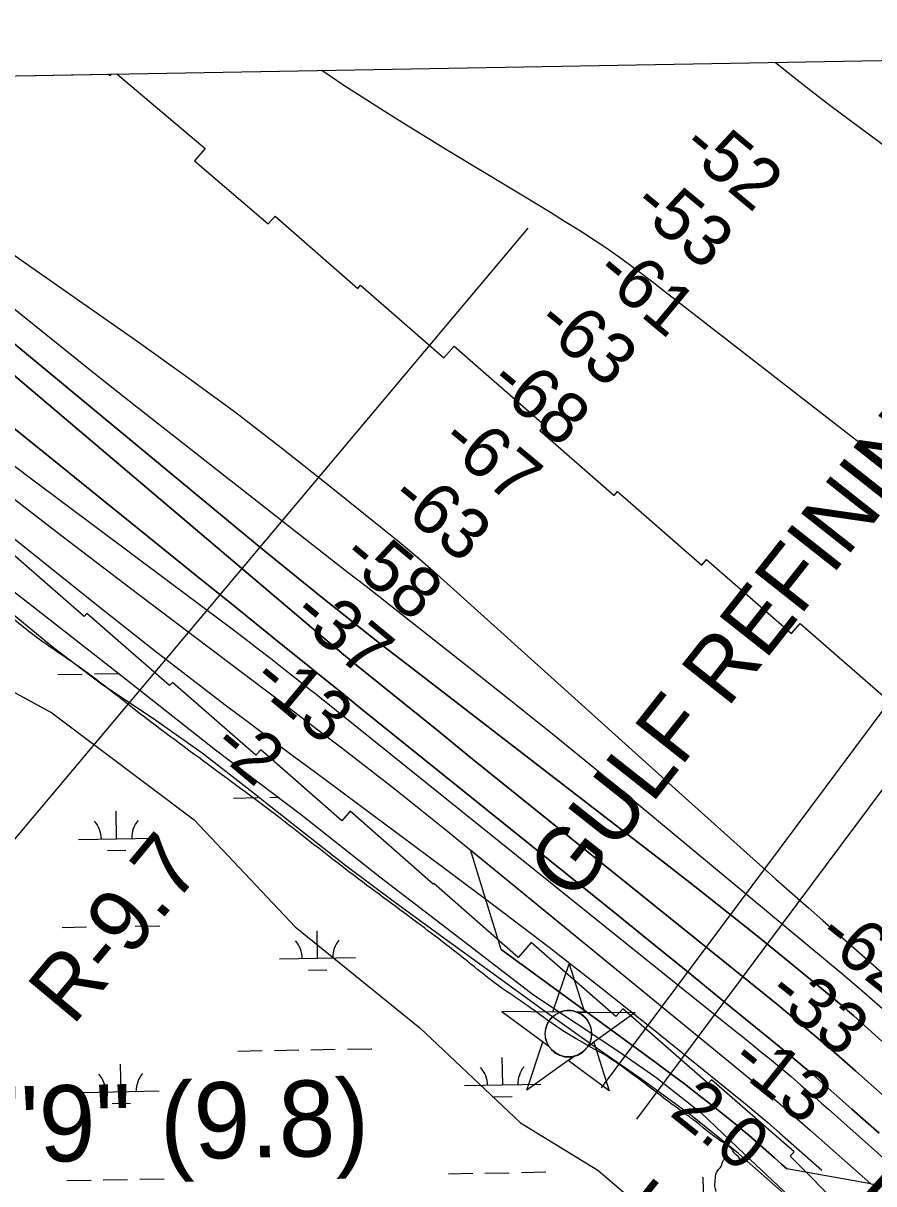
# Model space of a CAD drawing. Extents: x 3903937 to 3942190, y 260677 to 286651.
# Drawn here: x 3915846 to 3916965, y 282879 to 284405 of the extents above; entities that cross this region are included whole.
import ezdxf

# ---------------------------------------------------------------- set-up
doc = ezdxf.new("R2010")
doc.units = 0
for name, color, linetype in [('V-CHAN-NAID', 7, 'Continuous'), ('V-GRID-FRAM', 7, 'Continuous'), ('V-RIVR-EDGE', 7, 'Continuous'), ('V-RIVR-RANG', 7, 'Continuous'), ('V-RIVR-RANG-IDEN', 7, 'Continuous'), ('V-RRAP-FSHR', 7, 'Continuous'), ('V-RRAP-RVMT', 7, 'Continuous'), ('V-SITE-VEGE', 7, 'Continuous'), ('V-TOPO-DPTH', 7, 'Continuous'), ('V-TOPO-MAJR', 7, 'Continuous'), ('V-TOPO-MINR', 7, 'Continuous'), ('V-TOPO-WATR', 7, 'Continuous'), ('V-TOPO-WATR-IDEN', 7, 'Continuous'), ('V-UTIL-IDEN', 7, 'Continuous'), ('V-UTIL-LINE', 7, 'Continuous'), ('V-WETL-SWMP', 7, 'Continuous')]:
    doc.layers.add(name, color=color, linetype=linetype)

msp = doc.modelspace()

# ---------------------------------------------------------------- linework, layer by layer
at = {"layer": 'V-CHAN-NAID'}
for points in [[(3916552.3, 283104.9), (3916542.7, 283105), (3916563.9, 283168.4), (3916584.1, 283104.7), (3916574.5, 283104.7), (3916572.9, 283105.3), (3916570.8, 283105.9), (3916568.8, 283106.4), (3916566.7, 283106.7), (3916565.6, 283106.8), (3916564, 283106.9), (3916562.3, 283106.9), (3916561, 283106.8), (3916559, 283106.6), (3916557.7, 283106.4), (3916555.9, 283106), (3916554.4, 283105.6), (3916553.3, 283105.3)], [(3916552.3, 283104.9), (3916475.8, 283105.4), (3916537.4, 283060), (3916536.3, 283061.9), (3916535.5, 283063.6), (3916534.6, 283065.5), (3916533.9, 283067.6), (3916533.6, 283068.9), (3916533.2, 283070.5), (3916533, 283072), (3916532.8, 283073.6), (3916532.7, 283075.3), (3916532.7, 283076.9), (3916532.8, 283079), (3916533, 283080.6), (3916533.4, 283082.8), (3916533.8, 283084.7), (3916534.4, 283086.6), (3916535.1, 283088.3), (3916535.8, 283089.9), (3916536.6, 283091.4), (3916537.7, 283093.1), (3916538.7, 283094.6), (3916539.7, 283095.9), (3916540.7, 283097), (3916542, 283098.4), (3916543.1, 283099.3), (3916544.8, 283100.7), (3916546, 283101.6), (3916547.7, 283102.7), (3916549.4, 283103.6), (3916550.9, 283104.3)], [(3916574.5, 283104.7), (3916651, 283104.2), (3916588.8, 283059.7), (3916589.7, 283061.2), (3916590.7, 283063), (3916591.4, 283064.6), (3916592.1, 283066.5), (3916592.7, 283068.3), (3916593.1, 283070), (3916593.4, 283072), (3916593.6, 283073.6), (3916593.7, 283075.8), (3916593.7, 283077.8), (3916593.5, 283080), (3916593.3, 283081.8), (3916592.8, 283084), (3916592.1, 283086.2), (3916591.4, 283088.2), (3916590.7, 283089.6), (3916589.7, 283091.5), (3916588.7, 283093.2), (3916587.4, 283094.9), (3916586.2, 283096.5), (3916584.9, 283097.8), (3916583.3, 283099.4), (3916581.5, 283100.8), (3916579.9, 283102), (3916578, 283103.1), (3916576.5, 283103.9)], [(3916570.8, 283046.8), (3916508.5, 283002.2), (3916529.7, 283065.7), (3916537.4, 283060), (3916538, 283059.1), (3916539.4, 283057.2), (3916540.6, 283055.8), (3916542.1, 283054.3), (3916543.5, 283053), (3916544.9, 283051.9), (3916546.3, 283050.9), (3916548, 283049.9), (3916549.7, 283049), (3916551.5, 283048.1), (3916553, 283047.6), (3916554.6, 283047.1), (3916556.8, 283046.5), (3916558.4, 283046.2), (3916560.4, 283045.9), (3916561.9, 283045.8), (3916563.8, 283045.8), (3916565.5, 283045.9), (3916567.2, 283046.1), (3916569.1, 283046.4)], [(3916588.8, 283059.7), (3916596.6, 283065.2), (3916616.8, 283001.5), (3916563, 283041.2), (3916570.8, 283046.8), (3916572.4, 283047.2), (3916574, 283047.8), (3916576.2, 283048.7), (3916577.9, 283049.6), (3916579.8, 283050.7), (3916581.5, 283051.9), (3916583.1, 283053.2), (3916584.4, 283054.3), (3916585.8, 283055.8), (3916587, 283057.2), (3916588.1, 283058.6)]]:
    msp.add_lwpolyline(points, close=True, dxfattribs=at)
msp.add_circle((3916563.2, 283076.4), 30.5, dxfattribs=at)
at = {"layer": 'V-GRID-FRAM'}
msp.add_lwpolyline([(3907892.2, 284196.1), (3939773.2, 284757.2), (3940101.1, 266577.6), (3908204.3, 266016.2), (3907892.2, 284196.1)], dxfattribs=at)
at = {"layer": 'V-RIVR-EDGE'}
msp.add_spline([(3917425.1, 282263.8), (3917389, 282294.2), (3917376.9, 282301.5), (3917364.7, 282305.9), (3917358.9, 282312.7), (3917351.7, 282313.2), (3917339.5, 282313.8), (3917337.6, 282316.7), (3917335.7, 282327.9), (3917333.2, 282330.8), (3917324.5, 282334.2), (3917318.2, 282334.7), (3917313.8, 282338.1), (3917308, 282350.3), (3917295.5, 282366.8), (3917283.8, 282379), (3917272.2, 282386.3), (3917256.7, 282392.6), (3917245, 282398), (3917231.4, 282406.8), (3917219.3, 282412.6), (3917183.4, 282425.8), (3917138.3, 282440), (3917074.7, 282459.6), (3917032, 282479.1), (3916988.4, 282500.1), (3916967.5, 282515.7), (3916953.5, 282531.3), (3916939.4, 282546.9), (3916923.4, 282556.6), (3916909.4, 282558.6), (3916896.3, 282564), (3916886.6, 282574.7), (3916876.4, 282580.1), (3916858.4, 282585), (3916838.5, 282588.4), (3916812.3, 282597.2), (3916792, 282609.9), (3916782.3, 282615.7), (3916776, 282619.6), (3916763.8, 282627.4), (3916749.3, 282634.3), (3916741, 282637.7), (3916730.4, 282642.1), (3916723.6, 282648.4), (3916721.7, 282654.3), (3916721.7, 282661.1), (3916724.1, 282668.3), (3916732.9, 282687.7), (3916733.4, 282696), (3916730.5, 282710.6), (3916725.2, 282723.7), (3916724.8, 282730.5), (3916727.2, 282735.3), (3916735.5, 282744.1), (3916736.9, 282748.4), (3916736.5, 282752.3), (3916730.2, 282755.7), (3916729.2, 282758.2), (3916731.6, 282760.1), (3916731.6, 282763.5), (3916727.8, 282770.8), (3916727.3, 282772.7), (3916727.8, 282778.1), (3916727.8, 282783.9), (3916726.9, 282799), (3916725.5, 282818.4), (3916729.9, 282838.8), (3916731.4, 282846.1), (3916733.8, 282854.8), (3916737.7, 282862.1), (3916742.1, 282864.5), (3916751.8, 282863.5), (3916755.7, 282865.4), (3916757.2, 282868.8), (3916756.2, 282873.2), (3916756.2, 282883.9), (3916757.7, 282894.1), (3916764, 282902.3), (3916767, 282910.1), (3916770.4, 282913), (3916781, 282908.1), (3916789.3, 282907.6), (3916789.3, 282910), (3916782, 282918.8), (3916778.7, 282923.6), (3916763.6, 282935.3), (3916726.8, 282963.6), (3916714.2, 282972.9), (3916689, 282991.4), (3916632.3, 283034.2), (3916610, 283048.9), (3916578, 283066.9), (3916543, 283088.9), (3916510.1, 283112.7), (3916469.8, 283140.5), (3916444.2, 283160.5), (3916369, 283219), (3916281.3, 283284.2), (3916175.1, 283366.6), (3916089.8, 283429.9), (3915988, 283506.4), (3915917.7, 283560), (3915863.9, 283597.5), (3915811.6, 283639.9), (3915738.9, 283704.7)], degree=3, dxfattribs=at)
at = {"layer": 'V-RIVR-RANG'}
msp.add_line((3915532.3, 282972.2), (3916510.4, 284135.6), dxfattribs=at)
at = {"layer": 'V-RRAP-FSHR'}
msp.add_lwpolyline([(3917074.9, 282641.2), (3917017.9, 282698.1), (3916960.6, 282754), (3916903.8, 282810.2), (3916846.5, 282866.5), (3916786.6, 282919.1), (3916724.3, 282969.3), (3916659.5, 283016.2), (3916593.8, 283061.7), (3916528.8, 283108.4), (3916464, 283155.3), (3916399.2, 283202.2), (3916334.5, 283249.3), (3916270.4, 283297.1), (3916207.5, 283346.5), (3916144.8, 283396.3), (3916081.5, 283445.3), (3916016.3, 283491.4), (3915949.6, 283535.4), (3915885.9, 283583.8), (3915824.2, 283634.5)], dxfattribs=at)
at = {"layer": 'V-RRAP-RVMT'}
for p, q in [((3915090, 284322.8), (3915958.5, 284338.1)), ((3915958.5, 284338.1), (3915960.7, 284336.2)), ((3915960.7, 284336.2), (3915962.3, 284338.1)), ((3915962.3, 284338.1), (3915969.3, 284338.3)), ((3915969.3, 284338.3), (3916085.5, 284240.2)), ((3916085.5, 284240.2), (3916071.7, 284223.9)), ((3916071.7, 284223.9), (3916168.3, 284141)), ((3916168.3, 284141), (3916177.4, 284151.3)), ((3916177.4, 284151.3), (3916286.1, 284056.3)), ((3916286.1, 284056.3), (3916289.7, 284060.5)), ((3916289.7, 284060.5), (3916399.2, 283964.9)), ((3916399.2, 283964.9), (3916412.7, 283980.3)), ((3916412.7, 283980.3), (3916531.6, 283876.4)), ((3916531.6, 283876.4), (3916525.4, 283869.4)), ((3916525.4, 283869.4), (3916623.2, 283784)), ((3916623.2, 283784), (3916627.7, 283789.2)), ((3916627.7, 283789.2), (3916738.4, 283692.6)), ((3915926.5, 283624.8), (3915822.8, 283715.3)), ((3916738.4, 283692.6), (3916744.8, 283699.9)), ((3916744.8, 283699.9), (3916856.3, 283602.4)), ((3915930.1, 283628.9), (3915926.5, 283624.8)), ((3916038.8, 283534), (3915930.1, 283628.9)), ((3916856.3, 283602.4), (3916868, 283615.8)), ((3916868, 283615.8), (3916980.7, 283517.4)), ((3916042.5, 283538.2), (3916038.8, 283534)), ((3916152.2, 283442.4), (3916042.5, 283538.2)), ((3916158.5, 283449.6), (3916152.2, 283442.4)), ((3916265.1, 283356.4), (3916158.5, 283449.6)), ((3916276, 283368.8), (3916265.1, 283356.4)), ((3916385.5, 283273.1), (3916276, 283368.8)), ((3916386.1, 283273.8), (3916385.5, 283273.1)), ((3916497.1, 283176.8), (3916386.1, 283273.8)), ((3916514.1, 283196.3), (3916497.1, 283176.8)), ((3916625.6, 283098.9), (3916514.1, 283196.3)), ((3916634.7, 283109.3), (3916625.6, 283098.9)), ((3916747, 283011.1), (3916634.7, 283109.3)), ((3916751.2, 283015.9), (3916747, 283011.1)), ((3916860.1, 282920.9), (3916751.2, 283015.9)), ((3916854.7, 282915.5), (3916860.1, 282920.9)), ((3916930.3, 282839.7), (3916854.7, 282915.5))]:
    msp.add_line(p, q, dxfattribs=at)
at = {"layer": 'V-SITE-VEGE'}
for p, q in [((3915712.2, 283591.8), (3915883.9, 283498.1)), ((3915883.9, 283498.1), (3916071.2, 283357.6)), ((3916071.2, 283357.6), (3916203.8, 283217)), ((3916203.8, 283217), (3916367.7, 283084.3)), ((3916367.7, 283084.3), (3916500.3, 282959.4)), ((3916500.3, 282959.4), (3916601.8, 282897)), ((3916601.8, 282897), (3917405.5, 282210))]:
    msp.add_line(p, q, dxfattribs=at)
at = {"layer": 'V-TOPO-DPTH'}
for points in [[(3915710, 284086.2), (3916138.8, 283731.5), (3916164.1, 283710.8), (3916189.4, 283690.1), (3916214.7, 283669.5), (3916240.2, 283649), (3916265.7, 283628.7), (3916291.4, 283608.4), (3916317.1, 283588.3), (3916342.9, 283568.3), (3916695.1, 283296.7), (3916733.4, 283266.8), (3916771.6, 283236.8), (3916809.5, 283206.3), (3916847.2, 283175.7), (3916905.9, 283127.5), (3916914.1, 283120.7), (3916922.2, 283113.9), (3916930.2, 283106.9), (3916938.2, 283099.9), (3916975.3, 283066.8)], [(3916975.3, 283066.8), (3916938.2, 283099.9), (3916930.2, 283106.9), (3916922.2, 283113.9), (3916914.1, 283120.7), (3916905.9, 283127.5), (3916847.2, 283175.7), (3916809.5, 283206.3), (3916771.6, 283236.8), (3916733.4, 283266.8), (3916695.1, 283296.7), (3916342.9, 283568.3), (3916317.1, 283588.3), (3916291.4, 283608.4), (3916265.7, 283628.7), (3916240.2, 283649), (3916214.7, 283669.5), (3916189.4, 283690.1), (3916164.1, 283710.8), (3916138.8, 283731.5), (3915710, 284086.2)], [(3917139.6, 282850.9), (3916940.9, 283027.3), (3916915.1, 283049.9), (3916889, 283072.3), (3916862.7, 283094.3), (3916836.1, 283116), (3916519.5, 283371.3), (3916477.1, 283405.5), (3916434.6, 283439.7), (3916392.2, 283474), (3916349.8, 283508.2), (3916284.7, 283560.9), (3916274.9, 283568.9), (3916265.1, 283576.9), (3916255.4, 283585), (3916245.8, 283593.1), (3915749.5, 284013.5)], [(3917139.6, 282850.9), (3916940.9, 283027.3), (3916915.1, 283049.9), (3916889, 283072.3), (3916862.7, 283094.3), (3916836.1, 283116), (3916519.5, 283371.3), (3916477.1, 283405.5), (3916434.6, 283439.7), (3916392.2, 283474), (3916349.8, 283508.2), (3916284.7, 283560.9), (3916274.9, 283568.9), (3916265.1, 283576.9), (3916255.4, 283585), (3916245.8, 283593.1), (3915749.5, 284013.5)], [(3916971.9, 282945.7), (3916935.9, 282977.4), (3916884.3, 283022.6), (3916874, 283031.5), (3916863.6, 283040.4), (3916853.1, 283049.2), (3916842.6, 283057.9), (3916769.7, 283117.2), (3916722.7, 283155.4), (3916675.6, 283193.6), (3916628.5, 283231.7), (3916581.3, 283269.8), (3916290.4, 283504.1), (3916264.7, 283524.8), (3916239.1, 283545.5), (3916213.4, 283566.2), (3916187.7, 283586.9), (3916124.5, 283638), (3916067.2, 283684.2), (3916009.9, 283730.5), (3915952.6, 283776.7), (3915895.2, 283822.9), (3915673.8, 284001.2)], [(3915673.8, 284001.2), (3915895.2, 283822.9), (3915952.6, 283776.7), (3916009.9, 283730.5), (3916067.2, 283684.2), (3916124.5, 283638), (3916187.7, 283586.9), (3916213.4, 283566.2), (3916239.1, 283545.5), (3916264.7, 283524.8), (3916290.4, 283504.1), (3916581.3, 283269.8), (3916628.5, 283231.7), (3916675.6, 283193.6), (3916722.7, 283155.4), (3916769.7, 283117.2), (3916842.6, 283057.9), (3916853.1, 283049.2), (3916863.6, 283040.4), (3916874, 283031.5), (3916884.3, 283022.6), (3916935.9, 282977.4), (3916971.9, 282945.7)], [(3915796.4, 283808.7), (3915897.2, 283731), (3915998.4, 283653.8), (3916141.4, 283545.9), (3916171.5, 283523.1), (3916201.5, 283500.4), (3916231.6, 283477.6), (3916261.6, 283454.7), (3916269, 283449.1), (3916302.5, 283423.3), (3916335.9, 283397.3), (3916369, 283370.9), (3916401.9, 283344.3), (3916773.8, 283040.4), (3916800.9, 283018), (3916827.8, 282995.5), (3916854.4, 282972.6), (3916880.9, 282949.6), (3916960.8, 282879.2), (3917057.6, 282869.5)], [(3916434.2, 283318), (3916773.8, 283040.4), (3916800.9, 283018), (3916827.8, 282995.5), (3916854.4, 282972.6), (3916880.9, 282949.6), (3916960.8, 282879.2)], [(3916960.8, 282879.2), (3916850.3, 282898.7), (3916843.5, 282904.7), (3916834.1, 282913), (3916800.6, 282942.5), (3916796.1, 282946.4), (3916791.6, 282950.2), (3916787.1, 282953.9), (3916782.5, 282957.7), (3916753.8, 282980.6), (3916734.7, 282995.6), (3916715.6, 283010.5), (3916696.2, 283025.1), (3916676.7, 283039.5), (3916474.9, 283186.9), (3916434.2, 283318)]]:
    msp.add_lwpolyline(points, dxfattribs=at)
at = {"layer": 'V-TOPO-MAJR'}
for points in [[(3917013.1, 284356.6), (3917248.8, 284114.3), (3917252.2, 284103.6), (3917251.6, 284094.6), (3917245.3, 284088.1), (3917235.1, 284083.3), (3917216.6, 284084.5), (3917198.8, 284088), (3917182.1, 284095), (3917166.1, 284104.5), (3916932.3, 284277.9), (3916907, 284296.8), (3916882, 284316), (3916857.2, 284335.5), (3916834.8, 284353.5)], [(3915822.6, 284039), (3915880.8, 283992), (3915939.2, 283945.3), (3915997.7, 283898.9), (3916056.5, 283852.8), (3916271.9, 283684.3), (3916297, 283664.7), (3916322.1, 283645), (3916347.2, 283625.3), (3916372.2, 283605.6), (3916432.4, 283558.3), (3916487.3, 283514.7), (3916542, 283470.8), (3916596.4, 283426.5), (3916650.5, 283381.9), (3916901.3, 283173.6), (3916921.8, 283156.4), (3916942.2, 283139), (3916962.5, 283121.5), (3916982.7, 283103.8), (3917085.6, 283012.8), (3917151, 282954.8), (3917216.3, 282896.6), (3917281.5, 282838.3)]]:
    msp.add_lwpolyline(points, dxfattribs=at)
at = {"layer": 'V-TOPO-MINR'}
for points in [[(3917126.2, 283713.3), (3916681.6, 284058.5), (3916677.2, 284061.9), (3916672.8, 284065.3), (3916668.4, 284068.6), (3916664, 284071.9), (3916643.4, 284087.3), (3916628.6, 284098.1), (3916613.6, 284108.7), (3916598.3, 284118.9), (3916582.9, 284128.9), (3916576.8, 284132.7), (3916558.2, 284144.4), (3916539.5, 284156), (3916520.8, 284167.5), (3916502, 284178.9), (3916403, 284238.4), (3916335.2, 284280.3), (3916268, 284323.2), (3916238.7, 284343)], [(3915154, 284323.9), (3915210.9, 284276.7), (3915268.2, 284230), (3915596.7, 283966.6), (3915696.3, 283887.4), (3915796.4, 283808.7), (3915897.2, 283731), (3915998.4, 283653.8), (3916141.4, 283545.9), (3916171.5, 283523.1), (3916201.5, 283500.4), (3916231.6, 283477.6), (3916261.6, 283454.7), (3916269, 283449.1), (3916302.5, 283423.3), (3916335.9, 283397.3), (3916369, 283370.9), (3916401.9, 283344.3), (3916773.8, 283040.4), (3916800.9, 283018), (3916827.8, 282995.5), (3916854.4, 282972.6), (3916880.9, 282949.6), (3916960.8, 282879.2)], [(3915807.6, 284118.3), (3915997.5, 283985.9), (3916061, 283940.6), (3916123.9, 283894.4), (3916185.8, 283846.9), (3916247, 283798.5), (3916340.5, 283722.9), (3916354.4, 283711.5), (3916368.1, 283700), (3916381.6, 283688.2), (3916395, 283676.4), (3916708.2, 283393.8), (3916750.7, 283355.7), (3916793.2, 283317.6), (3916835.9, 283279.8), (3916878.7, 283242.1), (3916897.8, 283225.3), (3916931.1, 283196), (3916964.3, 283166.7), (3916997.6, 283137.3), (3917030.8, 283107.9), (3917371.1, 282806.3)], [(3915710, 284086.2), (3916138.8, 283731.5), (3916164.1, 283710.8), (3916189.4, 283690.1), (3916214.7, 283669.5), (3916240.2, 283649), (3916265.7, 283628.7), (3916291.4, 283608.4), (3916317.1, 283588.3), (3916342.9, 283568.3), (3916695.1, 283296.7), (3916733.4, 283266.8), (3916771.6, 283236.8), (3916809.5, 283206.3), (3916847.2, 283175.7), (3916905.9, 283127.5), (3916914.1, 283120.7), (3916922.2, 283113.9), (3916930.2, 283106.9), (3916938.2, 283099.9), (3916975.3, 283066.8)], [(3915749.5, 284013.5), (3916245.8, 283593.1), (3916255.4, 283585), (3916265.1, 283576.9), (3916274.9, 283568.9), (3916284.7, 283560.9), (3916349.8, 283508.2), (3916392.2, 283474), (3916434.6, 283439.7), (3916477.1, 283405.5), (3916519.5, 283371.3), (3916836.1, 283116), (3916862.7, 283094.3), (3916889, 283072.3), (3916915.1, 283049.9), (3916940.9, 283027.3), (3917139.6, 282850.9)], [(3915673.8, 284001.2), (3915895.2, 283822.9), (3915952.6, 283776.7), (3916009.9, 283730.5), (3916067.2, 283684.2), (3916124.5, 283638), (3916187.7, 283586.9), (3916213.4, 283566.2), (3916239.1, 283545.5), (3916264.7, 283524.8), (3916290.4, 283504.1), (3916581.3, 283269.8), (3916628.5, 283231.7), (3916675.6, 283193.6), (3916722.7, 283155.4), (3916769.7, 283117.2), (3916842.6, 283057.9), (3916853.1, 283049.2), (3916863.6, 283040.4), (3916874, 283031.5), (3916884.3, 283022.6), (3916935.9, 282977.4), (3916971.9, 282945.7)], [(3915517.1, 283981.1), (3915943, 283640.3), (3915980.6, 283610.4), (3916018.4, 283580.7), (3916056.4, 283551.3), (3916094.6, 283522.1), (3916113.7, 283507.5), (3916142.5, 283485.8), (3916171.3, 283464.1), (3916200.1, 283442.5), (3916229.1, 283421), (3916398.9, 283295.1), (3916468.5, 283242.9), (3916537.7, 283190.1), (3916606.2, 283136.5), (3916674.4, 283082.3), (3916778, 282998.8), (3916793.9, 282985.9), (3916809.7, 282972.8), (3916825.3, 282959.5), (3916840.7, 282946), (3916896.5, 282897)], [(3915817.6, 283835.7), (3915855.5, 283807.3), (3916117.4, 283611.3), (3916135.4, 283597.7), (3916153.4, 283583.9), (3916171.3, 283570.1), (3916189.1, 283556.1), (3916215.6, 283535.2), (3916220.1, 283531.6), (3916224.6, 283528.1), (3916229.1, 283524.5), (3916233.6, 283520.9), (3916780.6, 283081.6), (3916792.3, 283072.2), (3916804.1, 283062.7), (3916815.8, 283053.1), (3916827.5, 283043.6), (3916845.7, 283028.7), (3916848.3, 283026.5), (3916850.8, 283024.4), (3916853.4, 283022.2), (3916855.9, 283020.1), (3916868.9, 283008.7), (3916878, 283000.8), (3916887, 282992.9), (3916895.9, 282985), (3916904.9, 282977.1), (3917364.6, 282567.7)]]:
    msp.add_lwpolyline(points, dxfattribs=at)
at = {"layer": 'V-TOPO-WATR'}
msp.add_lwpolyline([(3916474.9, 283186.9), (3916676.7, 283039.5), (3916696.2, 283025.1), (3916715.6, 283010.5), (3916734.7, 282995.6), (3916753.8, 282980.6), (3916782.5, 282957.7), (3916787.1, 282953.9), (3916791.6, 282950.2), (3916796.1, 282946.4), (3916800.6, 282942.5), (3916834.1, 282913), (3916843.5, 282904.7), (3916850.3, 282898.7)], dxfattribs=at)
at = {"layer": 'V-UTIL-LINE'}
for p, q in [((3916606.8, 283005.3), (3917621.5, 284367.3)), ((3916653.2, 282964.1), (3917699.7, 284368.7))]:
    msp.add_line(p, q, dxfattribs=at)
at = {"layer": 'V-WETL-SWMP'}
for p, q in [((3915747.6, 283725.1), (3915855.9, 283640.6)), ((3915855.9, 283640.6), (3915978.4, 283544.8)), ((3915891.8, 283548.7), (3915923.8, 283549.3)), ((3915939.8, 283549.6), (3915971.6, 283550.1)), ((3915978.4, 283544.8), (3916098.9, 283449.7)), ((3916098.9, 283449.7), (3916212.1, 283364.1)), ((3916122.7, 283386.3), (3916154.7, 283386.8)), ((3916170.7, 283387.1), (3916181.4, 283387.3)), ((3915969, 283332.8), (3915968.4, 283368.8)), ((3916212.1, 283364.1), (3916315.1, 283282.6)), ((3915919, 283331.9), (3916019, 283333.7)), ((3915957.3, 283317.2), (3915981.3, 283317.6)), ((3916315.1, 283282.6), (3916422, 283200.6)), ((3915897.7, 283216.1), (3915929.7, 283216.7)), ((3915945.7, 283216.9), (3915977.7, 283217.5)), ((3915993.7, 283217.8), (3916025.7, 283218.4)), ((3916233.3, 283175.6), (3916232.6, 283211.6)), ((3916422, 283200.6), (3916517.3, 283127.6)), ((3916183.3, 283174.7), (3916283.3, 283176.4)), ((3916221.6, 283159.9), (3916245.6, 283160.4)), ((3916517.3, 283127.6), (3916629.4, 283052.8)), ((3916128.6, 283053.6), (3916160.6, 283054.2)), ((3916176.6, 283054.5), (3916208.6, 283055)), ((3916224.6, 283055.3), (3916256.5, 283055.9)), ((3916272.5, 283056.2), (3916304.5, 283056.7)), ((3916629.4, 283052.8), (3916678, 283019.3)), ((3915974.9, 283000.2), (3915974.3, 283036.2)), ((3916476.7, 283009), (3916476.1, 283045)), ((3916678, 283019.3), (3916737.5, 282972.5)), ((3916426.7, 283008.1), (3916526.7, 283009.9)), ((3915924.9, 282999.3), (3916024.9, 283001.1)), ((3916465, 282993.4), (3916489, 282993.8)), ((3915963.2, 282984.5), (3915987.2, 282985)), ((3916737.5, 282972.5), (3916794.7, 282918)), ((3916794.7, 282918), (3916853.6, 282862.7)), ((3915903.5, 282883.5), (3915935.5, 282884)), ((3915951.5, 282884.3), (3915983.5, 282884.9)), ((3915999.5, 282885.2), (3916031.5, 282885.7)), ((3916405.4, 282892.3), (3916437.4, 282892.9)), ((3916453.4, 282893.2), (3916485.3, 282893.7)), ((3916501.3, 282894), (3916533.3, 282894.6)), ((3916741, 282851.8), (3916740.3, 282887.8))]:
    msp.add_line(p, q, dxfattribs=at)
for centre, start, end in [((3915913.8, 283332.3), 0.2366, 41.7802), ((3916024.3, 283334.3), 140.2366, 181.7802), ((3916178, 283175.1), 0.2366, 41.7802), ((3916288.5, 283177), 140.2366, 181.7802), ((3915919.6, 282999.7), 0.2366, 41.7802), ((3916030.1, 283001.6), 140.2366, 181.7802), ((3916421.5, 283008.5), 0.2366, 41.7802), ((3916531.9, 283010.5), 140.2366, 181.7802)]:
    msp.add_arc(centre, 35.2, start, end, dxfattribs=at)

# ---------------------------------------------------------------- texts
at = {"layer": 'V-CHAN-NAID'}
msp.add_text('JUMP "9" (9.8)', height=100, rotation=1.1211, dxfattribs=at).set_placement((3915419.3, 282899.2))
at = {"layer": 'V-RIVR-RANG'}
for s, rotation, p in [('-52', 320.3031, (3916708.6, 284237.6)), ('-53', 320.3031, (3916644.1, 284161.2)), ('-61', 320.3031, (3916594.8, 284072.1)), ('-63', 320.3031, (3916517.6, 284006.3)), ('-68', 320.3031, (3916455.6, 283927.8)), ('-67', 320.3031, (3916391.7, 283850.9)), ('-63', 320.3031, (3916325.4, 283775.9)), ('-58', 320.3031, (3916261.7, 283698.8)), ('-37', 320.3031, (3916196.7, 283622.9)), ('-13', 320.3031, (3916143.8, 283536.8)), ('-2', 320.0183, (3916091.9, 283450.2)), ('-62', 321.5637, (3916887.2, 283199.7)), ('-33', 321.5637, (3916821.5, 283124.1)), ('-13', 321.5637, (3916772.8, 283035.1)), ('2.0', 321.2783, (3916694.5, 282970.2))]:
    msp.add_text(s, height=67, rotation=rotation, dxfattribs=at).set_placement(p)
at = {"layer": 'V-RIVR-RANG-IDEN'}
for s, rotation, p in [('R-9.7', 50.1615, (3915911.2, 283085.4)), ('R-9.5', 51.4221, (3916576.2, 282629.1))]:
    msp.add_text(s, height=83, rotation=rotation, dxfattribs=at).set_placement(p)
at = {"layer": 'V-TOPO-WATR-IDEN'}
msp.add_text('L.W.R.P.', height=83, rotation=317.9407, dxfattribs=at).set_placement((3916931.3, 282855.5))
at = {"layer": 'V-UTIL-IDEN'}
msp.add_text('GULF REFINING', height=83, rotation=51.7037, dxfattribs=at).set_placement((3916569.4, 283247))

doc.saveas('drawing.dxf')
